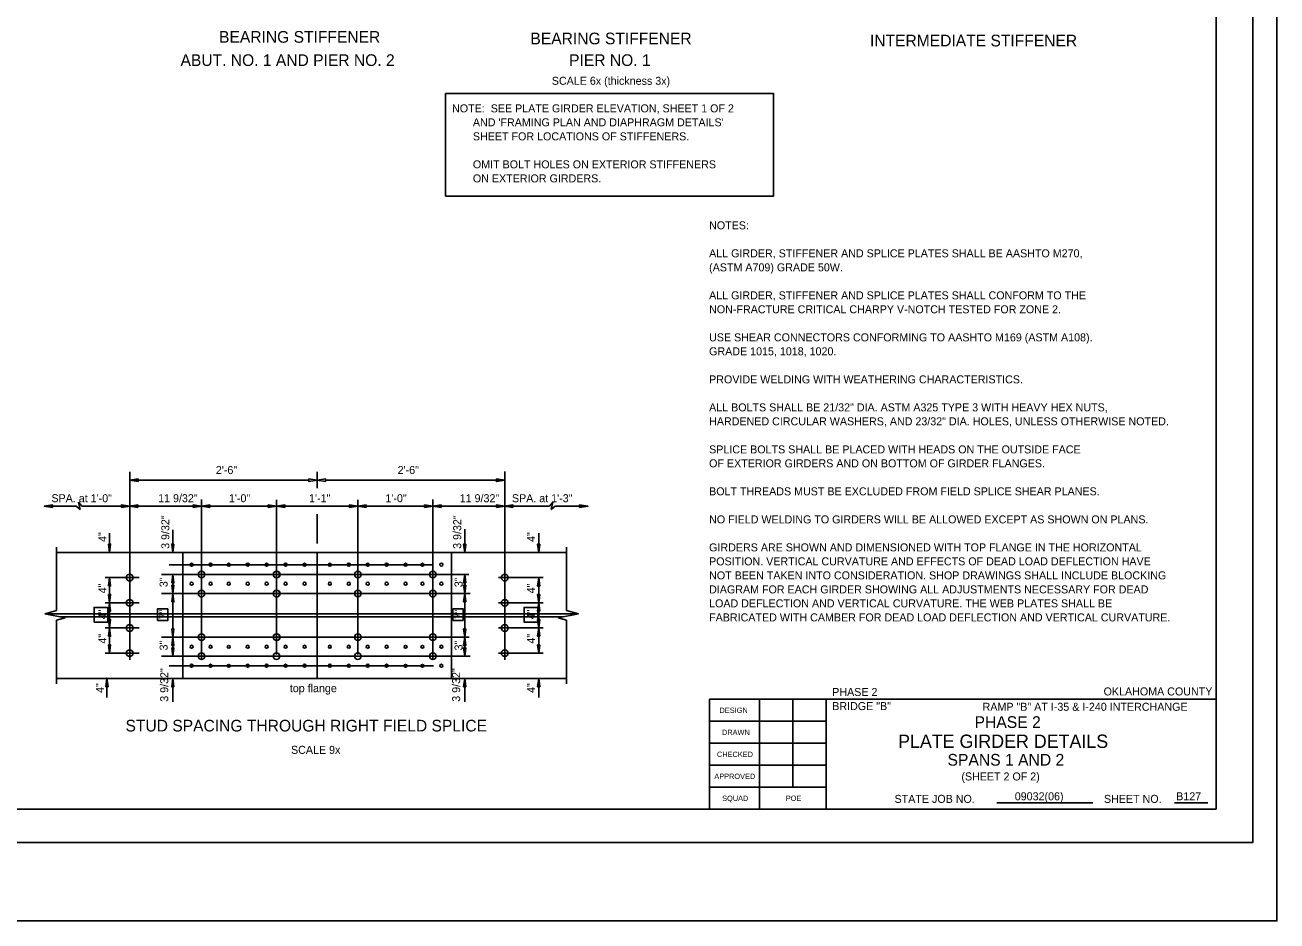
# Model space of a CAD drawing. Extents: x 4944 to 17449, y 3824 to 49087.
# Drawn here: x 7527 to 9330, y 8331 to 9621 of the extents above; entities that cross this region are included whole.
import ezdxf

# ---------------------------------------------------------------- set-up
doc = ezdxf.new("R2010")
doc.units = 0
for name, color, linetype in [('1', 7, 'Continuous'), ('2', 7, 'Continuous'), ('36_S_LINES', 7, 'Continuous'), ('37_S_TXT', 7, 'Continuous'), ('3A', 7, 'Continuous'), ('7', 7, 'Continuous'), ('BEAM', 7, 'Continuous'), ('DIM', 7, 'Continuous'), ('ID', 7, 'Continuous'), ('Level 14', 7, 'Continuous'), ('Level 17', 7, 'Continuous'), ('Level 25', 7, 'Continuous'), ('Level 35', 7, 'Continuous'), ('REVISED', 7, 'Continuous')]:
    doc.layers.add(name, color=color, linetype=linetype)

# ---------------------------------------------------------------- blocks, each defined once
blk = doc.blocks.new('4MH')
at = {"layer": 'Level 35'}
for radius, start, end in [(0.0945, 112.5426, 157.4574), (0.06, 112.5426, 157.4574), (0.06, 22.5426, 67.4574), (0.0945, 22.5426, 67.4574), (0.0945, 202.5426, 247.4574), (0.06, 202.5426, 247.4574), (0.06, 292.5426, 337.4574), (0.0945, 292.5426, 337.4574)]:
    blk.add_arc((0, 0), radius, start, end, dxfattribs=at)

msp = doc.modelspace()

# ---------------------------------------------------------------- linework, layer by layer
at = {"layer": '1'}
for centre, start, end in [((7767, 8844.4), 0, 180), ((7767, 8844.4), 180, 0), ((7794.3, 8844.5), 0, 180), ((7794.3, 8844.5), 180, 0), ((7820.4, 8844.4), 0, 180), ((7820.4, 8844.4), 180, 0), ((7847.7, 8844.5), 0, 180), ((7847.7, 8844.5), 180, 0), ((7875, 8844.4), 0, 180), ((7875, 8844.4), 180, 0), ((7902.3, 8844.5), 0, 180), ((7902.3, 8844.5), 180, 0), ((7929.6, 8844.4), 0, 180), ((7929.6, 8844.4), 180, 0), ((7966, 8844.4), 0, 180), ((7966, 8844.4), 180, 0), ((7993.3, 8844.5), 0, 180), ((7993.3, 8844.5), 180, 0), ((8020.5, 8844.4), 0, 180), ((8020.5, 8844.4), 180, 0), ((8047.8, 8844.5), 0, 180), ((8047.8, 8844.5), 180, 0), ((8075.1, 8844.4), 0, 180), ((8075.1, 8844.4), 180, 0), ((8099.3, 8844.4), 0, 180), ((8099.3, 8844.4), 180, 0), ((8126.6, 8844.5), 0, 180), ((8126.6, 8844.5), 180, 0), ((7767, 8817.1), 0, 180), ((7767, 8817.1), 180, 0), ((7794.3, 8817.1), 0, 180), ((7794.3, 8817.1), 180, 0), ((7820.4, 8817.1), 0, 180), ((7820.4, 8817.1), 180, 0), ((7847.7, 8817.1), 0, 180), ((7847.7, 8817.1), 180, 0), ((7875, 8817.1), 0, 180), ((7875, 8817.1), 180, 0), ((7902.3, 8817.1), 0, 180), ((7902.3, 8817.1), 180, 0), ((7929.6, 8817.1), 0, 180), ((7929.6, 8817.1), 180, 0), ((7966, 8817.1), 0, 180), ((7966, 8817.1), 180, 0), ((7993.3, 8817.1), 0, 180), ((7993.3, 8817.1), 180, 0), ((8020.5, 8817.1), 0, 180), ((8020.5, 8817.1), 180, 0), ((8047.8, 8817.1), 0, 180), ((8047.8, 8817.1), 180, 0), ((8075.1, 8817.1), 0, 180), ((8075.1, 8817.1), 180, 0), ((8099.3, 8817.1), 0, 180), ((8099.3, 8817.1), 180, 0), ((8126.6, 8817.1), 0, 180), ((8126.6, 8817.1), 180, 0), ((7767, 8726.3), 0, 180), ((7767, 8726.3), 180, 0), ((7794.3, 8726.3), 0, 180), ((7794.3, 8726.3), 180, 0), ((7820.4, 8726.2), 0, 180), ((7820.4, 8726.2), 180, 0), ((7847.7, 8726.3), 0, 180), ((7847.7, 8726.3), 180, 0), ((7875, 8726.3), 0, 180), ((7875, 8726.3), 180, 0), ((7902.3, 8726.3), 0, 180), ((7902.3, 8726.3), 180, 0), ((7929.6, 8726.3), 0, 180), ((7929.6, 8726.3), 180, 0), ((7966, 8726.3), 0, 180), ((7966, 8726.3), 180, 0), ((7993.3, 8726.3), 0, 180), ((7993.3, 8726.3), 180, 0), ((8020.5, 8726.3), 0, 180), ((8020.5, 8726.3), 180, 0), ((8047.8, 8726.3), 0, 180), ((8047.8, 8726.3), 180, 0), ((8075.1, 8726.2), 0, 180), ((8075.1, 8726.2), 180, 0), ((8099.3, 8726.2), 0, 180), ((8099.3, 8726.2), 180, 0), ((8126.6, 8726.3), 0, 180), ((8126.6, 8726.3), 180, 0), ((7767, 8699), 0, 180), ((7767, 8699), 180, 0), ((7794.3, 8698.9), 0, 180), ((7794.3, 8698.9), 180, 0), ((7820.4, 8698.8), 0, 180), ((7820.4, 8698.8), 180, 0), ((7847.7, 8698.9), 0, 180), ((7847.7, 8698.9), 180, 0), ((7875, 8699), 0, 180), ((7875, 8699), 180, 0), ((7902.3, 8698.9), 0, 180), ((7902.3, 8698.9), 180, 0), ((7929.6, 8699), 0, 180), ((7929.6, 8699), 180, 0), ((7966, 8699), 0, 180), ((7966, 8699), 180, 0), ((7993.3, 8698.9), 0, 180), ((7993.3, 8698.9), 180, 0), ((8020.5, 8699), 0, 180), ((8020.5, 8699), 180, 0), ((8047.8, 8698.9), 0, 180), ((8047.8, 8698.9), 180, 0), ((8075.1, 8698.8), 0, 180), ((8075.1, 8698.8), 180, 0), ((8099.3, 8698.8), 0, 180), ((8099.3, 8698.8), 180, 0), ((8126.6, 8698.9), 0, 180), ((8126.6, 8698.9), 180, 0)]:
    msp.add_arc(centre, 2.13, start, end, dxfattribs=at)
at = {"layer": '2'}
msp.add_line((7947.8, 8680.8), (7947.8, 8862.1), dxfattribs=at)
at = {"layer": '36_S_LINES'}
for p, q in [((7947.8, 8978.3), (7947.8, 8954.5)), ((7682.3, 8966), (7935.8, 8966)), ((7959.8, 8966), (8217.8, 8966)), ((7600.8, 8928.6), (7554.7, 8928.6)), ((7606.5, 8924), (7600.8, 8928.6)), ((7604, 8934.6), (7606.5, 8924)), ((7608.8, 8928.6), (7604, 8934.6)), ((7916.3, 8928.6), (7608.9, 8928.6)), ((7916.3, 8928.6), (7979.2, 8928.6)), ((7979.2, 8928.6), (8282.2, 8928.6)), ((8282.2, 8928.6), (8287, 8934.5)), ((8287, 8934.5), (8284.5, 8924)), ((8284.5, 8924), (8290.3, 8928.6)), ((8290.3, 8928.6), (8333.2, 8928.6)), ((7947.8, 8917.4), (7947.8, 8875.2)), ((7648.8, 8889.7), (7648.8, 8862.1)), ((7739.9, 8894.7), (7739.9, 8862.1)), ((8160.2, 8895.7), (8160.2, 8862.1)), ((8266.7, 8889.7), (8266.7, 8862.1)), ((7572.6, 8869.7), (7572.6, 8778.3)), ((8307, 8869.7), (8307, 8778.3)), ((7648.8, 8826), (7648.8, 8789.6)), ((7739.9, 8830.2), (7739.9, 8802.9)), ((7739.9, 8830.2), (7739.9, 8825.7)), ((8160.2, 8830.2), (8160.2, 8802.9)), ((8266.7, 8826), (8266.7, 8789.6)), ((7739.9, 8753.3), (7739.9, 8802.9)), ((8160.2, 8748), (8160.2, 8802.9)), ((7648.8, 8753.3), (7648.8, 8780.6)), ((8266.7, 8753.3), (8266.7, 8780.6)), ((7572.6, 8778.3), (7555.6, 8773.5)), ((7555.6, 8773.5), (7584.7, 8767.8)), ((7584.7, 8767.8), (7572.6, 8764.4)), ((7572.6, 8764.4), (7572.6, 8672.7)), ((8324.1, 8773.5), (8295, 8767.8)), ((8295, 8767.8), (8307, 8764.4)), ((8307, 8778.3), (8324.1, 8773.5)), ((8307, 8764.4), (8307, 8672.7)), ((7648.8, 8716.8), (7648.8, 8753.3)), ((8266.7, 8716.8), (8266.7, 8753.3)), ((7739.9, 8712.7), (7739.9, 8740)), ((8160.2, 8712.7), (8160.2, 8740)), ((7739.9, 8712.6), (7739.9, 8717.2)), ((7645.1, 8680.7), (7645.1, 8653.1)), ((7739.9, 8680.7), (7739.9, 8647.2)), ((8160.2, 8680.7), (8160.2, 8647.2)), ((8266.7, 8680.7), (8266.7, 8653.1))]:
    msp.add_line(p, q, dxfattribs=at)
for points in [[(7689.8, 8964), (7677.8, 8966), (7689.8, 8968)], [(7935.8, 8968), (7947.8, 8966), (7935.8, 8964)], [(7959.8, 8964), (7947.8, 8966), (7959.8, 8968)], [(8205.8, 8968), (8217.8, 8966), (8205.8, 8964)], [(7566.7, 8926.6), (7566.7, 8930.6), (7554.7, 8928.6)], [(7665.9, 8926.6), (7665.9, 8930.6), (7677.9, 8928.6)], [(7689.6, 8926.6), (7689.6, 8930.6), (7677.6, 8928.6)], [(7769.4, 8926.6), (7769.4, 8930.6), (7781.4, 8928.6)], [(7793.1, 8926.6), (7793.1, 8930.6), (7781.1, 8928.6)], [(7877.3, 8926.6), (7877.3, 8930.6), (7889.3, 8928.6)], [(7901.3, 8926.6), (7901.3, 8930.6), (7889.3, 8928.6)], [(7994.3, 8926.6), (7994.3, 8930.6), (8006.3, 8928.6)], [(8018.3, 8926.6), (8018.3, 8930.6), (8006.3, 8928.6)], [(8102.4, 8926.6), (8102.4, 8930.6), (8114.4, 8928.6)], [(8126.1, 8926.6), (8126.1, 8930.6), (8114.1, 8928.6)], [(8205.9, 8926.6), (8205.9, 8930.6), (8217.9, 8928.6)], [(8229.6, 8926.6), (8229.6, 8930.6), (8217.6, 8928.6)], [(8325.7, 8926.6), (8325.7, 8930.6), (8337.7, 8928.6)], [(7647.3, 8874.1), (7650.3, 8874.1), (7648.8, 8862.1)], [(7741.4, 8874.1), (7738.4, 8874.1), (7739.9, 8862.1)], [(8161.7, 8874.1), (8158.6, 8874.1), (8160.2, 8862.1)], [(8268.2, 8874.1), (8265.2, 8874.1), (8266.7, 8862.1)], [(7647.3, 8813.8), (7650.3, 8813.8), (7648.8, 8825.8)], [(7738.4, 8818.2), (7741.4, 8818.2), (7739.9, 8830.2)], [(7738.4, 8814.9), (7741.4, 8814.9), (7739.9, 8802.9)], [(8161.7, 8818.2), (8158.6, 8818.2), (8160.2, 8830.2)], [(8161.7, 8814.9), (8158.6, 8814.9), (8160.2, 8802.9)], [(8268.2, 8813.7), (8265.2, 8813.7), (8266.7, 8825.7)], [(7647.3, 8801.6), (7650.3, 8801.6), (7648.8, 8789.6)], [(7738.4, 8790.9), (7741.4, 8790.9), (7739.9, 8802.9)], [(8161.7, 8790.9), (8158.6, 8790.9), (8160.2, 8802.9)], [(8268.2, 8801.6), (8265.2, 8801.6), (8266.7, 8789.6)], [(7647.3, 8777.7), (7650.3, 8777.7), (7648.8, 8789.7)], [(8268.2, 8777.7), (8265.2, 8777.7), (8266.7, 8789.7)], [(7647.3, 8765.3), (7650.3, 8765.3), (7648.8, 8753.3)], [(8268.2, 8765.3), (8265.2, 8765.3), (8266.7, 8753.3)], [(7647.3, 8741.3), (7650.3, 8741.3), (7648.8, 8753.3)], [(7738.4, 8752), (7741.4, 8752), (7739.9, 8740)], [(8161.7, 8752), (8158.6, 8752), (8160.2, 8740)], [(8268.2, 8741.3), (8265.2, 8741.3), (8266.7, 8753.3)], [(7647.3, 8729), (7650.3, 8729), (7648.8, 8717.1)], [(7738.4, 8728), (7741.4, 8728), (7739.9, 8740)], [(7738.4, 8724.7), (7741.4, 8724.7), (7739.9, 8712.7)], [(8161.7, 8728), (8158.6, 8728), (8160.2, 8740)], [(8161.7, 8724.7), (8158.6, 8724.7), (8160.2, 8712.7)], [(8268.2, 8729), (8265.2, 8729), (8266.7, 8717.1)], [(7643.5, 8668.7), (7646.6, 8668.7), (7645.1, 8680.7)], [(7741.4, 8668.7), (7738.4, 8668.7), (7739.9, 8680.7)], [(8161.7, 8668.7), (8158.6, 8668.7), (8160.2, 8680.7)], [(8268.2, 8668.7), (8265.2, 8668.7), (8266.7, 8680.7)]]:
    msp.add_lwpolyline(points, close=True, dxfattribs=at)
at = {"layer": '37_S_TXT'}
msp.add_lwpolyline([(5873.7, 10635.5), (9329.7, 10635.5), (9329.7, 8331.5), (5873.7, 8331.5)], close=True, dxfattribs=at)
at = {"layer": '3A'}
for p, q in [((7677.8, 8707.7), (7677.8, 8978.3)), ((8217.8, 8707.7), (8217.8, 8978.7)), ((7781.3, 8707.7), (7781.3, 8938.3)), ((7889.3, 8715.2), (7889.3, 8937.7)), ((8006.3, 8715.2), (8006.3, 8937.7)), ((8114.3, 8707.7), (8114.3, 8938.3)), ((7642.3, 8825.8), (7691.3, 8825.8)), ((8166, 8830.2), (7723.6, 8830.2)), ((8273.3, 8825.8), (8208.8, 8825.8)), ((8167.9, 8802.9), (7723.6, 8802.9)), ((7642.3, 8789.6), (7691.3, 8789.6)), ((8273.3, 8789.6), (8208.8, 8789.6)), ((7642.3, 8753.3), (7691.3, 8753.3)), ((8273.3, 8753.3), (8208.8, 8753.3)), ((8166.8, 8740), (7723.6, 8740)), ((7642.3, 8717.1), (7691.3, 8717.1)), ((8168.1, 8712.6), (7723.6, 8712.6)), ((8273.3, 8717.1), (8208.8, 8717.1))]:
    msp.add_line(p, q, dxfattribs=at)
for points in [[(8132.6, 9375.2), (8604.9, 9375.2), (8604.9, 9522.8), (8132.6, 9522.8)], [(7626.6, 8761.9), (7626.6, 8783), (7646.2, 8783), (7646.2, 8761.9)], [(7717.8, 8764.2), (7717.8, 8780.7), (7732.8, 8780.7), (7732.8, 8764.2)], [(8158, 8764.2), (8158, 8780.7), (8143.1, 8780.7), (8143.1, 8764.2)], [(8265.4, 8761.9), (8265.4, 8783), (8245.8, 8783), (8245.8, 8761.9)]]:
    msp.add_lwpolyline(points, close=True, dxfattribs=at)
at = {"layer": '7'}
for p, q in [((7556.4, 8773.7), (8323.3, 8773.7)), ((7577.7, 8769.2), (8301.9, 8769.2))]:
    msp.add_line(p, q, dxfattribs=at)
at = {"layer": 'DEFPOINTS'}
for p, q in [((7734.6, 8844.1), (8115.3, 8844.1)), ((7734.6, 8698.8), (8115.3, 8698.8))]:
    msp.add_line(p, q, dxfattribs=at)
at = {"layer": 'DIM'}
msp.add_lwpolyline([(6030.9, 10556.3), (9294.9, 10556.3), (9294.9, 8444.3), (6030.9, 8444.3)], close=True, dxfattribs=at)
at = {"layer": 'Level 14'}
for p, q in [((8512.5, 8492.3), (8512.5, 8650.7)), ((8512.5, 8650.7), (9242.1, 8650.7)), ((8680.5, 8492.3), (8680.5, 8650.8)), ((8680.5, 8492.3), (8680.5, 8650.8))]:
    msp.add_line(p, q, dxfattribs=at)
msp.add_lwpolyline([(9242.1, 8492.3), (6218.1, 8492.3), (6218.1, 10508.3), (9242.1, 10508.3)], close=True, dxfattribs=at)
at = {"layer": 'Level 17'}
for p, q in [((8584.5, 8492.3), (8584.5, 8650.8)), ((8632.5, 8524), (8632.5, 8650.8)), ((8926.4, 8501.5), (9064.6, 8501.5)), ((8926.4, 8501.5), (9064.6, 8501.5)), ((9182.2, 8501.5), (9230.4, 8501.5)), ((9182.2, 8501.5), (9230.4, 8501.5))]:
    msp.add_line(p, q, dxfattribs=at)
for points in [[(8680.5, 8619), (8512.5, 8619)], [(8680.5, 8587.3), (8512.5, 8587.3)], [(8680.5, 8555.6), (8512.5, 8555.6)], [(8680.5, 8524), (8512.5, 8524)]]:
    msp.add_lwpolyline(points, dxfattribs=at)
at = {"layer": 'Level 25'}
for p, q in [((7572.6, 8862.1), (8307, 8862.1)), ((7754.3, 8680.8), (7754.3, 8862.1)), ((8141.2, 8680.8), (8141.2, 8862.1)), ((7572.6, 8680.8), (8307, 8680.8))]:
    msp.add_line(p, q, dxfattribs=at)
for centre in [(7781.3, 8830.2), (7889.3, 8830.2), (7889.5, 8830.2), (8006.3, 8830.2), (8114.3, 8830.2), (7677.8, 8825.8), (8217.8, 8825.8), (7781.3, 8802.8), (7889.3, 8802.8), (7889.5, 8802.8), (8006.3, 8802.9), (8114.3, 8802.8), (7677.8, 8789.6), (8217.8, 8789.6), (7677.8, 8753.3), (7781.3, 8740.1), (7889.3, 8740.1), (7889.5, 8740.1), (8006.3, 8740.1), (8114.3, 8740.1), (8217.8, 8753.3), (7677.8, 8717.1), (7781.3, 8712.7), (7889.3, 8712.7), (8006.3, 8712.7), (8114.3, 8712.7), (8217.8, 8717.1)]:
    msp.add_circle(centre, 4.79, dxfattribs=at)

# ---------------------------------------------------------------- block references
at = {"layer": 'Level 35', "xscale": 5, "yscale": 5}
msp.add_blockref('4MH', (7645.1, 8680.8), dxfattribs=at)

# ---------------------------------------------------------------- texts
at = {"layer": '3A'}
for s, height, p in [('NOTE:  SEE PLATE GIRDER ELEVATION, SHEET 1 OF 2 ', 11.52, (8142, 9495.7)), ("       AND 'FRAMING PLAN AND DIAPHRAGM DETAILS' ", 11.52, (8142, 9475.6)), ('       SHEET FOR LOCATIONS OF STIFFENERS. ', 11.52, (8142, 9455.4)), ('       OMIT BOLT HOLES ON EXTERIOR STIFFENERS ', 11.52, (8142, 9415.1)), ('       ON EXTERIOR GIRDERS.', 11.52, (8142, 9394.9)), ('NOTES:', 11.52, (8512.1, 9327.3)), ('ALL GIRDER, STIFFENER AND SPLICE PLATES SHALL BE AASHTO M270,', 11.52, (8512.1, 9287)), ('(ASTM A709) GRADE 50W.', 11.52, (8512.1, 9266.8)), ('ALL GIRDER, STIFFENER AND SPLICE PLATES SHALL CONFORM TO THE', 11.52, (8512.1, 9226.5)), ('NON-FRACTURE CRITICAL CHARPY V-NOTCH TESTED FOR ZONE 2.', 11.52, (8512.1, 9206.4)), ('USE SHEAR CONNECTORS CONFORMING TO AASHTO M169 (ASTM A108).', 11.52, (8512.1, 9166)), ('GRADE 1015, 1018, 1020.', 11.52, (8512.1, 9145.9)), ('PROVIDE WELDING WITH WEATHERING CHARACTERISTICS.  ', 11.52, (8512.1, 9105.5)), ('ALL BOLTS SHALL BE 21/32" DIA. ASTM A325 TYPE 3 WITH HEAVY HEX NUTS, ', 11.52, (8512.1, 9065.2)), ('HARDENED CIRCULAR WASHERS, AND 23/32" DIA. HOLES, UNLESS OTHERWISE NOTED.  ', 11.52, (8512.1, 9045.1)), ('SPLICE BOLTS SHALL BE PLACED WITH HEADS ON THE OUTSIDE FACE', 11.52, (8512.1, 9004.7)), ('OF EXTERIOR GIRDERS AND ON BOTTOM OF GIRDER FLANGES.  ', 11.52, (8512.1, 8984.6)), ('2\'-6"', 11.52, (7801.9, 8975)), ('2\'-6"', 11.52, (8063.6, 8975)), ('SPA. at 1\'-0"', 11.52, (7565.1, 8934.4)), ('11 9/32"', 11.52, (7718.8, 8934.4)), ('1\'-0"', 11.52, (7820.7, 8934.4)), ('1\'-1"', 11.52, (7936.1, 8934.4)), ('1\'-0"', 11.52, (8046, 8934.4)), ('11 9/32"', 11.52, (8153, 8934.4)), ('SPA. at 1\'-3"', 11.52, (8228.2, 8934.4)), ('BOLT THREADS MUST BE EXCLUDED FROM FIELD SPLICE SHEAR PLANES.', 11.52, (8512.1, 8944.3)), ('NO FIELD WELDING TO GIRDERS WILL BE ALLOWED EXCEPT AS SHOWN ON PLANS.', 11.52, (8512.1, 8903.9)), ('GIRDERS ARE SHOWN AND DIMENSIONED WITH TOP FLANGE IN THE HORIZONTAL', 11.52, (8512.1, 8863.6)), ('POSITION. VERTICAL CURVATURE AND EFFECTS OF DEAD LOAD DEFLECTION HAVE ', 11.52, (8512.1, 8843.5)), ('NOT BEEN TAKEN INTO CONSIDERATION. SHOP DRAWINGS SHALL INCLUDE BLOCKING ', 11.52, (8512.1, 8823.3)), ('DIAGRAM FOR EACH GIRDER SHOWING ALL ADJUSTMENTS NECESSARY FOR DEAD ', 11.52, (8512.1, 8803.1)), ('LOAD DEFLECTION AND VERTICAL CURVATURE. THE WEB PLATES SHALL BE ', 11.52, (8512.1, 8783)), ('FABRICATED WITH CAMBER FOR DEAD LOAD DEFLECTION AND VERTICAL CURVATURE.', 11.52, (8512.1, 8762.8)), ('PHASE 2', 11.52, (8689.4, 8655.4)), ('OKLAHOMA COUNTY', 11.52, (9080.1, 8656.2)), ('BRIDGE "B"', 11.52, (8689.4, 8635.1)), ('RAMP "B" AT I-35 & I-240 INTERCHANGE', 11.52, (8905.9, 8634.1)), ('(SHEET 2 OF 2)', 11.5, (8875.4, 8533.8)), ('09032(06)', 11.52, (8952.2, 8505.2)), ('B127', 11.52, (9184.6, 8505.2))]:
    msp.add_text(s, height=height, dxfattribs=at).set_placement(p)
for s, p in [('3 9/32"', (7734.9, 8867.2)), ('3 9/32"', (8155.1, 8867.2)), ('4"', (7644.4, 8877.2)), ('4"', (8261.4, 8877.2)), ('4"', (7644.4, 8803.1)), ('3"', (7732.4, 8812.1)), ('3"', (8157.1, 8812.1)), ('4"', (8261.4, 8803.1)), ('4"', (7644.4, 8765.9)), ('7"', (7732.2, 8766)), ('7"', (8157.1, 8766)), ('4"', (8261.4, 8765.9)), ('4"', (7644.4, 8730.8)), ('4"', (8261.4, 8730.8)), ('3"', (7732.4, 8721)), ('3"', (8157.1, 8721)), ('3 9/32"', (7733.3, 8647.1)), ('3 9/32"', (8153.6, 8647.1)), ('4"', (7640.6, 8659.8)), ('4"', (8261.4, 8659.8))]:
    msp.add_text(s, height=11.52, rotation=90, dxfattribs=at).set_placement(p)
at = {"layer": 'BEAM'}
for s, height, p in [('BEARING STIFFENER', 16.8, (7806.5, 9596)), ('BEARING STIFFENER', 16.8, (8254.8, 9593.7)), ('INTERMEDIATE STIFFENER', 16.8, (8743.7, 9590.7)), ('ABUT. NO. 1 AND PIER NO. 2', 16.8, (7751, 9562.5)), ('PIER NO. 1', 16.8, (8310.5, 9562.5)), ('STUD SPACING THROUGH RIGHT FIELD SPLICE', 16.8, (7671.8, 8604.3)), ('PLATE GIRDER DETAILS', 19.2, (8784.2, 8580.6))]:
    msp.add_text(s, height=height, dxfattribs=at).set_placement(p)
at = {"layer": 'DEFPOINTS'}
for s, height, p in [('SCALE 6x (thickness 3x)', 11.52, (8285.6, 9535.4)), ('top flange', 11.52, (7908.4, 8660.9)), ('PHASE 2', 16.88, (8894.3, 8609.4)), ('SCALE 9x', 11.52, (7910.1, 8572.1))]:
    msp.add_text(s, height=height, dxfattribs=at).set_placement(p)
at = {"layer": 'ID'}
msp.add_text('SPANS 1 AND 2', height=16.875, dxfattribs=at).set_placement((8855.4, 8555.1))
at = {"layer": 'REVISED'}
for s, height, p in [('DESIGN', 7.68, (8527.1, 8631)), ('DRAWN', 7.68, (8530.6, 8599.3)), ('CHECKED', 7.68, (8523.4, 8567.6)), ('APPROVED', 7.68, (8519.6, 8535.9)), ('SQUAD', 7.68, (8530.9, 8504.2)), ('POE', 7.68, (8622.5, 8504.3)), ('STATE JOB NO.', 11.52, (8779.1, 8501.5)), ('STATE JOB NO.', 11.52, (8779.1, 8501.5)), ('SHEET NO. ', 11.52, (9080.6, 8501.5)), ('SHEET NO. ', 11.52, (9080.6, 8501.5))]:
    msp.add_text(s, height=height, dxfattribs=at).set_placement(p)

doc.saveas('drawing.dxf')
